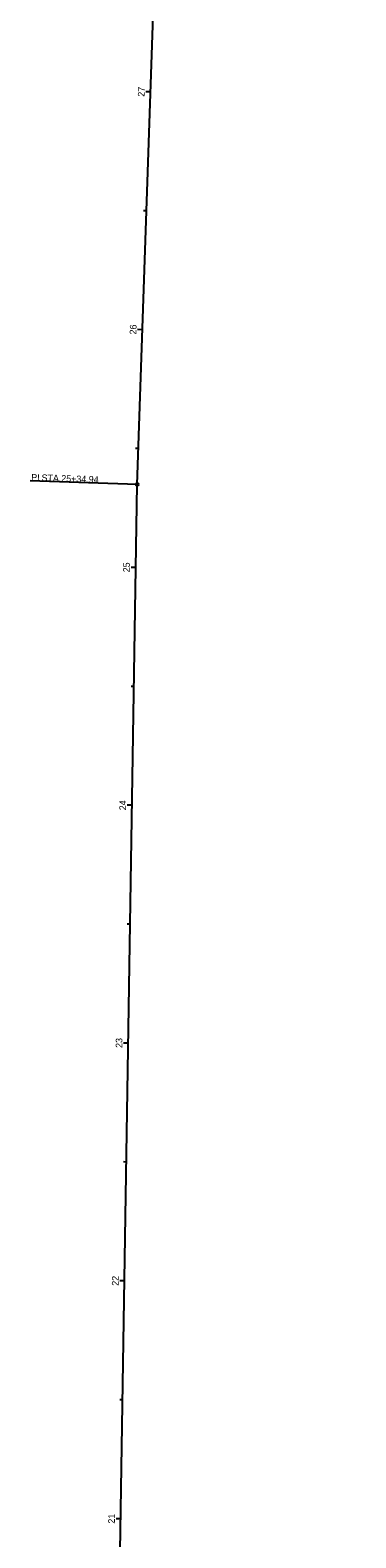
# Model space of a CAD drawing. Extents: x 140402 to 140969, y 345095 to 350073.
# Drawn here: x 140402 to 140539, y 346948 to 347582 of the extents above; entities that cross this region are included whole.
import ezdxf

# ---------------------------------------------------------------- set-up
doc = ezdxf.new("R2010")
doc.units = 0
for name, color, linetype in [('SC_Scratch1', 7, 'Continuous'), ('SN_X_Public', 7, 'Continuous'), ('SV_X_Control_Cells_Found', 7, 'Continuous'), ('SV_X_Mon_Cells_Found', 7, 'Continuous')]:
    doc.layers.add(name, color=color, linetype=linetype)

msp = doc.modelspace()

# ---------------------------------------------------------------- linework, layer by layer
at = {"layer": 'SC_Scratch1'}
msp.add_line((140446.87, 347390.84), (140401.9, 347392.39), dxfattribs=at)
msp.add_circle((140446.87, 347390.84), 0.6, dxfattribs=at)
at = {"layer": 'SN_X_Public'}
for p, q in [((140452.54, 347555.81), (140450.54, 347555.88)), ((140450.82, 347505.84), (140449.62, 347505.88)), ((140449.1, 347455.87), (140447.1, 347455.94)), ((140447.39, 347405.9), (140446.19, 347405.94)), ((140446.32, 347355.91), (140444.32, 347355.94)), ((140445.53, 347305.92), (140444.33, 347305.93)), ((140444.75, 347255.92), (140442.75, 347255.95)), ((140443.96, 347205.93), (140442.76, 347205.95)), ((140443.18, 347155.93), (140441.18, 347155.97)), ((140442.39, 347105.94), (140441.19, 347105.96)), ((140441.6, 347055.95), (140439.6, 347055.98)), ((140440.82, 347005.95), (140439.62, 347005.97)), ((140440.03, 346955.96), (140438.03, 346955.99))]:
    msp.add_line(p, q, dxfattribs=at)
at = {"layer": 'SV_X_Control_Cells_Found'}
msp.add_line((140431.46, 346410.7), (140446.87, 347390.84), dxfattribs=at)
at = {"layer": 'SV_X_Mon_Cells_Found'}
for p, q in [((140446.87, 347390.84), (140538.87, 350068.61)), ((140432.44, 346472.94), (140446.87, 347390.84))]:
    msp.add_line(p, q, dxfattribs=at)

# ---------------------------------------------------------------- texts
at = {"layer": 'SC_Scratch1'}
for s, p in [('PI', (140402.31, 347392.41)), (' STA. ', (140405.62, 347392.3)), ('25+34.94', (140414.94, 347391.98))]:
    msp.add_text(s, height=2.8, rotation=358.0322, dxfattribs=at).set_placement(p)
at = {"layer": 'SN_X_Public'}
for s, rotation, p in [('27', 88.0322, (140449.97, 347553.77)), ('26', 88.0322, (140446.53, 347453.82)), ('25', 89.09948, (140443.79, 347353.86)), ('24', 89.09948, (140442.21, 347253.8)), ('23', 89.09948, (140440.64, 347153.89)), ('22', 89.09948, (140439.07, 347053.89)), ('21', 89.09948, (140437.5, 346953.89))]:
    msp.add_text(s, height=2.8, rotation=rotation, dxfattribs=at).set_placement(p)

doc.saveas('drawing.dxf')
